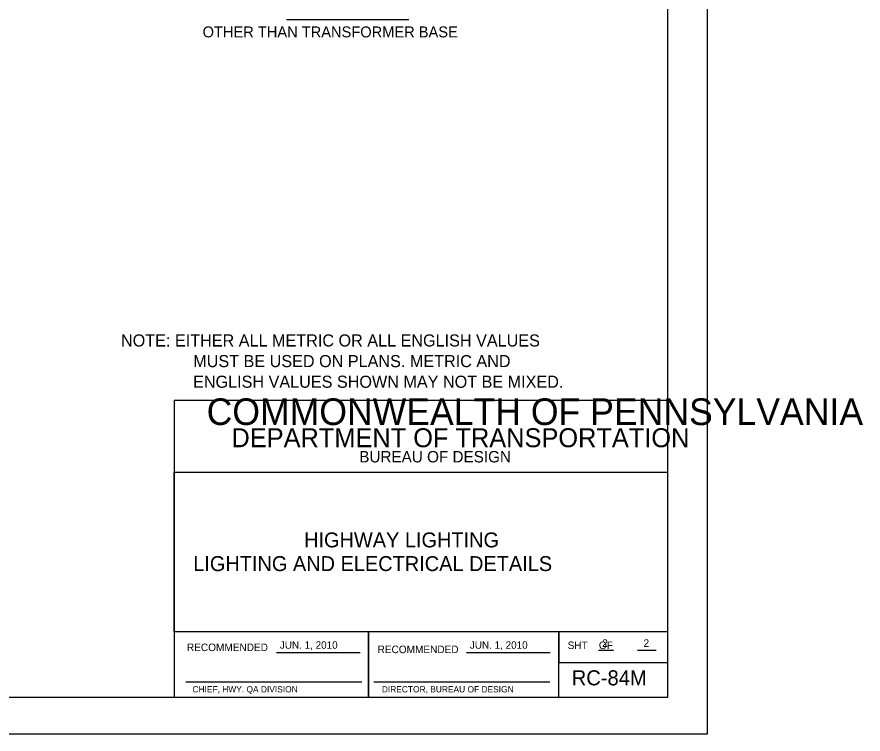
# Model space of a CAD drawing. Extents: x 638448 to 639352, y 297825 to 299013.
# Drawn here: x 639008.9 to 639351.8, y 297825.3 to 298115.7 of the extents above; entities that cross this region are included whole.
import ezdxf

# ---------------------------------------------------------------- set-up
doc = ezdxf.new("R2010")
doc.units = 0
for name, color, linetype in [('1', 7, 'Continuous'), ('3', 7, 'Continuous'), ('40', 7, 'Continuous'), ('PLT-BNDY', 7, 'Continuous')]:
    doc.layers.add(name, color=color, linetype=linetype)

msp = doc.modelspace()

# ---------------------------------------------------------------- linework, layer by layer
at = {"layer": '1'}
for p, q in [((639114.12, 297858.28), (639148, 297858.28)), ((639191.12, 297858.28), (639224.99, 297858.28)), ((639244.52, 297859.26), (639250.66, 297859.26)), ((639260.33, 297859.26), (639267.97, 297859.26)), ((639077.41, 297846.41), (639148.66, 297846.41)), ((639153.58, 297846.41), (639224.92, 297846.41))]:
    msp.add_line(p, q, dxfattribs=at)
msp.add_lwpolyline([(639272.65, 297840.29), (639272.65, 298404.29), (638486.65, 298404.29), (638486.65, 297840.29), (639272.65, 297840.29), (639272.65, 297866.65), (639072.65, 297866.65), (639072.65, 297931.33), (639272.65, 297931.33), (639272.65, 297960.29), (639072.65, 297960.29), (639072.65, 297840.29), (639151.45, 297840.29), (639151.45, 297866.65), (639151.45, 297840.29), (639228.45, 297840.29), (639228.45, 297866.65), (639228.45, 297854.33), (639272.65, 297854.33)], dxfattribs=at)
at = {"layer": '3'}
msp.add_line((639118.19, 298114.64), (639167.74, 298114.64), dxfattribs=at)
at = {"layer": 'PLT-BNDY'}
msp.add_lwpolyline([(638447.65, 298419.29), (639288.65, 298419.29), (639288.65, 297825.29), (638447.65, 297825.29)], close=True, dxfattribs=at)

# ---------------------------------------------------------------- texts
at = {"layer": '1'}
for s, height, p in [('COMMONWEALTH OF PENNSYLVANIA', 10.7834, (639085.8, 297950.43)), ('DEPARTMENT OF TRANSPORTATION', 7.6843, (639095.86, 297941.44)), ('BUREAU OF DESIGN', 4.6221, (639147.64, 297935.28)), ('HIGHWAY LIGHTING', 6.04, (639125.29, 297900.89)), ('LIGHTING AND ELECTRICAL DETAILS', 6.04, (639080.37, 297891.29)), ('2', 3.05, (639246.1, 297860.61)), ('2', 3.05, (639262.82, 297860.61)), ('RECOMMENDED', 3.048, (639077.82, 297858.88)), ('JUN. 1, 2010', 3, (639115.46, 297859.84)), ('RECOMMENDED', 3.048, (639155.06, 297858.05)), ('JUN. 1, 2010', 3, (639192.45, 297859.84)), ('SHT    OF', 3.048, (639232.06, 297859.72)), ('RC-84M', 6.096, (639233.74, 297845.01)), ('CHIEF, HWY. QA DIVISION', 2.54, (639080.06, 297842.15)), ('DIRECTOR, BUREAU OF DESIGN', 2.54, (639156.78, 297842.15))]:
    msp.add_text(s, height=height, dxfattribs=at).set_placement(p)
at = {"layer": '3'}
msp.add_text('OTHER THAN TRANSFORMER BASE', height=4.4323, dxfattribs=at).set_placement((639084.17, 298107.39))
at = {"layer": '40'}
for s, p in [('NOTE: EITHER ALL METRIC OR ALL ENGLISH VALUES', (639051.1, 297982.22)), ('MUST BE USED ON PLANS. METRIC AND', (639080.37, 297973.86)), ('ENGLISH VALUES SHOWN MAY NOT BE MIXED.', (639080.3, 297965.51))]:
    msp.add_text(s, height=4.9016, dxfattribs=at).set_placement(p)

doc.saveas('drawing.dxf')
